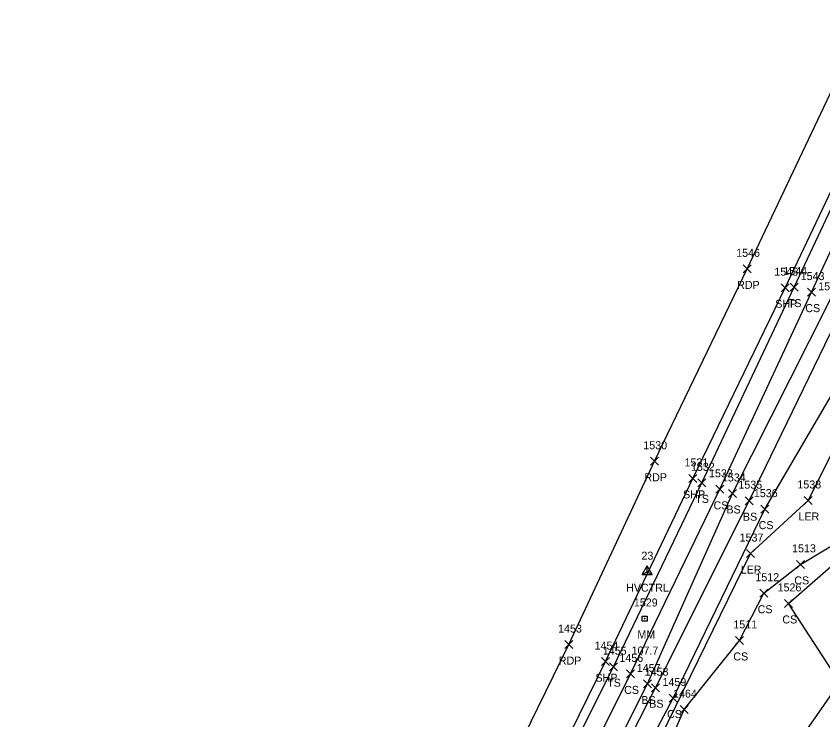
# Model space of a CAD drawing. Extents: x 1483143 to 1488182, y 802902 to 807581.
# Drawn here: x 1487426.2 to 1487627.8, y 805798.7 to 805974.5 of the extents above; entities that cross this region are included whole.
import ezdxf

# ---------------------------------------------------------------- set-up
doc = ezdxf.new("R2010")
doc.units = 0
for name, color, linetype in [('C_A', 7, 'Continuous'), ('C_I', 7, 'Continuous'), ('CPSM', 7, 'Continuous'), ('L_A', 7, 'Continuous'), ('L_I', 7, 'Continuous'), ('L_TIC', 7, 'Continuous'), ('LARO', 7, 'Continuous'), ('LELB', 7, 'Continuous'), ('P_A', 7, 'Continuous'), ('P_I', 7, 'Continuous'), ('P_TIC', 7, 'Continuous'), ('PET', 7, 'Continuous'), ('PSP', 7, 'Continuous'), ('S_A', 7, 'Continuous'), ('S_C', 7, 'Continuous'), ('S_I', 7, 'Continuous'), ('SRM', 7, 'Continuous')]:
    doc.layers.add(name, color=color, linetype=linetype)

msp = doc.modelspace()

# ---------------------------------------------------------------- linework, layer by layer
at = {"layer": 'CPSM'}
for p, q in [((1487582.67, 805835.01), (1487583.92, 805837.18)), ((1487585.17, 805835.01), (1487583.92, 805837.18)), ((1487583.92, 805835.74), (1487583.92, 805837.18)), ((1487582.67, 805835.01), (1487583.92, 805835.74)), ((1487582.67, 805835.01), (1487585.17, 805835.01)), ((1487583.92, 805835.74), (1487583.92, 805835.74)), ((1487583.92, 805835.74), (1487585.17, 805835.01))]:
    msp.add_line(p, q, dxfattribs=at)
at = {"layer": 'L_TIC'}
for points in [[(1487619.62, 805905.82), (1487621.62, 805907.82)], [(1487621.62, 805905.82), (1487619.62, 805907.82)], [(1487623.97, 805904.57), (1487625.97, 805906.57)], [(1487625.97, 805904.57), (1487623.97, 805906.57)], [(1487596.52, 805856.93), (1487598.52, 805858.93)], [(1487598.52, 805856.93), (1487596.52, 805858.93)], [(1487601.04, 805855.31), (1487603.04, 805857.31)], [(1487603.04, 805855.31), (1487601.04, 805857.31)], [(1487604.26, 805854.28), (1487606.26, 805856.28)], [(1487606.26, 805854.28), (1487604.26, 805856.28)], [(1487608.39, 805852.47), (1487610.39, 805854.47)], [(1487610.39, 805852.47), (1487608.39, 805854.47)], [(1487623.13, 805852.53), (1487625.13, 805854.53)], [(1487625.13, 805852.53), (1487623.13, 805854.53)], [(1487612.31, 805850.36), (1487614.31, 805852.36)], [(1487614.31, 805850.36), (1487612.31, 805852.36)], [(1487608.69, 805839.26), (1487610.69, 805841.26)], [(1487610.69, 805839.26), (1487608.69, 805841.26)], [(1487621.23, 805836.57), (1487623.23, 805838.57)], [(1487623.23, 805836.57), (1487621.23, 805838.57)], [(1487612.06, 805829.36), (1487614.06, 805831.36)], [(1487614.06, 805829.36), (1487612.06, 805831.36)], [(1487618.24, 805826.81), (1487620.24, 805828.81)], [(1487620.24, 805826.81), (1487618.24, 805828.81)], [(1487605.99, 805817.57), (1487607.99, 805819.57)], [(1487607.99, 805817.57), (1487605.99, 805819.57)], [(1487574.49, 805811.01), (1487576.49, 805813.01)], [(1487576.49, 805811.01), (1487574.49, 805813.01)], [(1487578.7, 805809.21), (1487580.7, 805811.21)], [(1487580.7, 805809.21), (1487578.7, 805811.21)], [(1487582.99, 805806.69), (1487584.99, 805808.69)], [(1487584.99, 805806.69), (1487582.99, 805808.69)], [(1487584.97, 805805.76), (1487586.97, 805807.76)], [(1487586.97, 805805.76), (1487584.97, 805807.76)], [(1487589.42, 805803.18), (1487591.42, 805805.18)], [(1487591.42, 805803.18), (1487589.42, 805805.18)], [(1487592.1, 805800.28), (1487594.1, 805802.28)], [(1487594.1, 805800.28), (1487592.1, 805802.28)]]:
    msp.add_lwpolyline(points, dxfattribs=at)
at = {"layer": 'LARO'}
for points in [[(1487519.52, 805604.85), (1487528.65, 805619.18), (1487533.33, 805631.91), (1487543.2, 805654.53), (1487555.05, 805678.36), (1487574.29, 805702.91), (1487587.86, 805730.92), (1487594.38, 805745.99), (1487602.81, 805747.66), (1487615.34, 805754.21), (1487619.89, 805765.57), (1487618.06, 805788.02), (1487632.01, 805808.09), (1487647.52, 805827.2), (1487662.05, 805847.87), (1487673.84, 805865.59), (1487680.96, 805879.63), (1487690.31, 805890.08), (1487695.82, 805899.7), (1487708.05, 805917.66), (1487714.11, 805946.66), (1487707.45, 805965.6), (1487711.43, 805989.94)], [(1487515.16, 805650.67), (1487521.68, 805670.54), (1487529.04, 805683.79), (1487537.68, 805691.67), (1487539.17, 805698.49), (1487539.8, 805706.7), (1487559.66, 805737.44), (1487565.81, 805755.37), (1487573.16, 805761.97), (1487578.75, 805774.48), (1487583.53, 805786.84), (1487609.69, 805840.26), (1487624.13, 805853.53), (1487644.16, 805893.39), (1487661.53, 805944.93), (1487666.95, 805964.97), (1487680.31, 805984.75)]]:
    msp.add_lwpolyline(points, dxfattribs=at)
at = {"layer": 'LELB'}
for points in [[(1487406.66, 805485.41), (1487431.45, 805531.24), (1487454.84, 805575.74), (1487473.75, 805612.05), (1487489.43, 805642.37), (1487507.64, 805678.53), (1487524.82, 805711.39), (1487541.86, 805746.09), (1487557.67, 805776.44), (1487575.49, 805812.01), (1487597.52, 805857.93), (1487620.62, 805906.82), (1487641.85, 805951.94), (1487662.18, 805996.35), (1487684.09, 806043.93), (1487694.42, 806066.95), (1487726.58, 806140.7), (1487745.85, 806185.55), (1487769.04, 806237.65), (1487788.58, 806284.85), (1487808.3, 806333.26), (1487827.52, 806379.6), (1487850.09, 806437.73)], [(1487410.04, 805483.24), (1487436.07, 805529.53), (1487459.78, 805575.03), (1487477.42, 805609.67), (1487492.45, 805639.09), (1487509.86, 805677.27), (1487528.68, 805708.85), (1487545.3, 805744.17), (1487561.79, 805774.32), (1487579.7, 805810.21), (1487602.04, 805856.31), (1487624.97, 805905.57), (1487645.72, 805950.02), (1487667.21, 805993.1), (1487687.16, 806043.23), (1487699.2, 806065.16), (1487730.65, 806138.87), (1487749.96, 806183.58), (1487772.93, 806235.17), (1487792.36, 806283.08), (1487812.9, 806331.5), (1487831.61, 806378.23), (1487855.61, 806436.65)], [(1487413.83, 805481.53), (1487440.22, 805526.89), (1487464.36, 805572.85), (1487481.71, 805606.55), (1487496.63, 805636.25), (1487514.9, 805673.97), (1487535.8, 805705.94), (1487549.07, 805741.59), (1487566.17, 805772.22), (1487583.99, 805807.69), (1487605.26, 805855.28), (1487629.33, 805903.01), (1487650.26, 805948.76), (1487670.48, 805991.25), (1487690.28, 806041.74), (1487702.22, 806061.37), (1487704.47, 806066.39), (1487735.28, 806136.71), (1487754, 806182.42), (1487776.55, 806233.47), (1487796.75, 806281.41), (1487816.88, 806330.25), (1487835.19, 806376.59), (1487859.78, 806434.97)], [(1487417, 805480.8), (1487442.28, 805525.8), (1487466.47, 805571.82), (1487483.84, 805604.86), (1487498.25, 805635.76), (1487518.24, 805671.86), (1487538.47, 805704.77), (1487552.2, 805739.67), (1487568.17, 805771.84), (1487585.97, 805806.76), (1487609.39, 805853.47), (1487632.34, 805900.81), (1487653.02, 805947.32), (1487672.59, 805990.01), (1487694.92, 806039.27), (1487707.45, 806059.25), (1487710.05, 806064.3), (1487737.97, 806135.43), (1487757.4, 806181.42), (1487778.76, 806231.94), (1487799.97, 806279.97), (1487818.92, 806329.91), (1487837.5, 806376), (1487863.45, 806433.38)], [(1487539.8, 805706.7), (1487554.99, 805738.51), (1487564.78, 805761.24), (1487572.42, 805770.06), (1487590.42, 805804.18), (1487613.31, 805851.36), (1487639.64, 805896.3), (1487657.07, 805945.9), (1487666.95, 805964.97), (1487675.89, 805987.99), (1487698.82, 806037.9), (1487713.56, 806059.8), (1487740.03, 806134.78), (1487759.8, 806179.98), (1487782.43, 806230.23), (1487804.48, 806278.55), (1487821.45, 806329.34), (1487839.66, 806374.66), (1487865.87, 806433.14)], [(1487632.01, 805808.09), (1487619.24, 805827.81), (1487647.66, 805852.57), (1487664.34, 805862.45), (1487671.06, 805867.81), (1487675.43, 805874.85), (1487684.3, 805891.3), (1487690.96, 805911.62), (1487700.16, 805920.88), (1487706.33, 805937.53), (1487707.55, 805950.23), (1487702.79, 805967.14), (1487703.8, 805992.98), (1487705.2, 806012.67), (1487721.31, 806024.08), (1487727.61, 806022.94), (1487740.06, 806020.89), (1487749.42, 806025.91)], [(1487578.75, 805774.48), (1487581.97, 805774.39), (1487587.14, 805787.59), (1487593.1, 805801.28), (1487606.99, 805818.57), (1487613.06, 805830.36), (1487622.23, 805837.57), (1487633.56, 805844.35), (1487644.82, 805850.87), (1487647.66, 805852.57)]]:
    msp.add_lwpolyline(points, dxfattribs=at)
at = {"layer": 'P_TIC'}
for points in [[(1487607.89, 805910.38), (1487609.89, 805912.38)], [(1487609.89, 805910.38), (1487607.89, 805912.38)], [(1487617.37, 805905.67), (1487619.37, 805907.67)], [(1487619.37, 805905.67), (1487617.37, 805907.67)], [(1487584.71, 805862.32), (1487586.71, 805864.32)], [(1487586.71, 805862.32), (1487584.71, 805864.32)], [(1487594.34, 805858.04), (1487596.34, 805860.04)], [(1487596.34, 805858.04), (1487594.34, 805860.04)], [(1487563.33, 805816.54), (1487565.33, 805818.54)], [(1487565.33, 805816.54), (1487563.33, 805818.54)], [(1487572.44, 805812.27), (1487574.44, 805814.27)], [(1487574.44, 805812.27), (1487572.44, 805814.27)]]:
    msp.add_lwpolyline(points, dxfattribs=at)
at = {"layer": 'PET'}
msp.add_lwpolyline([(1487396.33, 805490.41), (1487421.9, 805537.94), (1487444.13, 805580.16), (1487464.29, 805618.83), (1487479.8, 805648.39), (1487498.08, 805684.27), (1487514.57, 805717.15), (1487530.55, 805749.06), (1487547.16, 805782.47), (1487564.33, 805817.54), (1487585.71, 805863.32), (1487608.89, 805911.38), (1487630.35, 805956.68), (1487651.22, 806001.25), (1487672.63, 806048.33), (1487683.65, 806072.29), (1487715.61, 806144.47), (1487735.35, 806190.47), (1487757.48, 806241.03), (1487777.65, 806289.15), (1487798.25, 806337.46), (1487817.05, 806384.04), (1487839.67, 806441.4)], dxfattribs=at)
at = {"layer": 'PSP'}
msp.add_lwpolyline([(1487405.03, 805486.21), (1487429.8, 805532.42), (1487452.92, 805576.31), (1487472.37, 805613.24), (1487487.86, 805643.29), (1487506.35, 805679.4), (1487523.34, 805712.45), (1487540.38, 805746.64), (1487556.03, 805777.85), (1487573.44, 805813.27), (1487595.34, 805859.04), (1487618.37, 805906.67), (1487640.09, 805952.42), (1487660.18, 805997.21), (1487682.38, 806044.71), (1487693.04, 806068.56), (1487725.12, 806141.19), (1487744.39, 806185.87), (1487766.81, 806238.55), (1487786.8, 806285.64), (1487806.77, 806333.93), (1487825.55, 806380.21), (1487847.81, 806437.56)], dxfattribs=at)
at = {"layer": 'SRM'}
msp.add_lwpolyline([(1487582.63, 805824.67), (1487583.88, 805824.67), (1487583.88, 805823.42), (1487582.63, 805823.42)], close=True, dxfattribs=at)
msp.add_circle((1487583.26, 805824.05), 0.0833, dxfattribs=at)

# ---------------------------------------------------------------- texts
at = {"layer": 'C_A'}
msp.add_text('HVCTRL', height=2, dxfattribs=at).set_placement((1487578.62, 805830.74))
at = {"layer": 'C_I'}
msp.add_text('23', height=2, dxfattribs=at).set_placement((1487582.46, 805838.74))
at = {"layer": 'L_A'}
for s, p in [('TS', (1487619.03, 805901.82)), ('CS', (1487623.41, 805900.57)), ('TS', (1487595.93, 805852.93)), ('CS', (1487600.49, 805851.31)), ('BS', (1487603.7, 805850.28)), ('BS', (1487607.83, 805848.47)), ('LER', (1487621.72, 805848.53)), ('CS', (1487611.75, 805846.36)), ('LER', (1487607.27, 805835.26)), ('CS', (1487620.67, 805832.57)), ('CS', (1487611.5, 805825.36)), ('CS', (1487617.68, 805822.81)), ('CS', (1487605.43, 805813.57)), ('TS', (1487573.9, 805807.01)), ('CS', (1487578.14, 805805.21)), ('BS', (1487582.43, 805802.69)), ('BS', (1487584.41, 805801.76)), ('CS', (1487588.86, 805799.18))]:
    msp.add_text(s, height=2, dxfattribs=at).set_placement(p)
at = {"layer": 'L_I'}
for s, p in [('1544', (1487617.93, 805909.82)), ('1543', (1487622.27, 805908.57)), ('1542', (1487626.64, 805906.01)), ('1532', (1487594.82, 805860.93)), ('1533', (1487599.35, 805859.31)), ('1534', (1487602.57, 805858.28)), ('1535', (1487606.69, 805856.47)), ('1538', (1487621.44, 805856.53)), ('1536', (1487610.56, 805854.36)), ('1537', (1487607, 805843.26)), ('1513', (1487620.11, 805840.57)), ('1512', (1487610.94, 805833.36)), ('1526', (1487616.49, 805830.81)), ('1511', (1487605.43, 805821.57)), ('1455', (1487572.8, 805815.01)), ('1456', (1487576.95, 805813.21)), ('1457', (1487581.3, 805810.69)), ('1458', (1487583.27, 805809.76)), ('1459', (1487587.72, 805807.18)), ('1464', (1487590.36, 805804.28))]:
    msp.add_text(s, height=2, dxfattribs=at).set_placement(p)
at = {"layer": 'P_A'}
for s, p in [('RDP', (1487606.38, 805906.38)), ('SHP', (1487615.91, 805901.67)), ('RDP', (1487583.2, 805858.32)), ('SHP', (1487592.88, 805854.04)), ('RDP', (1487561.81, 805812.54)), ('SHP', (1487570.97, 805808.27))]:
    msp.add_text(s, height=2, dxfattribs=at).set_placement(p)
at = {"layer": 'P_I'}
for s, p in [('1546', (1487606.14, 805914.38)), ('1545', (1487615.68, 805909.67)), ('1530', (1487582.93, 805866.32)), ('1531', (1487593.22, 805862.04)), ('1453', (1487561.63, 805820.54)), ('1454', (1487570.75, 805816.27))]:
    msp.add_text(s, height=2, dxfattribs=at).set_placement(p)
at = {"layer": 'S_A'}
msp.add_text('MM', height=2, dxfattribs=at).set_placement((1487581.45, 805819.05))
at = {"layer": 'S_C'}
msp.add_text('107.7', height=2, dxfattribs=at).set_placement((1487580, 805815.05))
at = {"layer": 'S_I'}
msp.add_text('1529', height=2, dxfattribs=at).set_placement((1487580.56, 805827.05))

doc.saveas('drawing.dxf')
